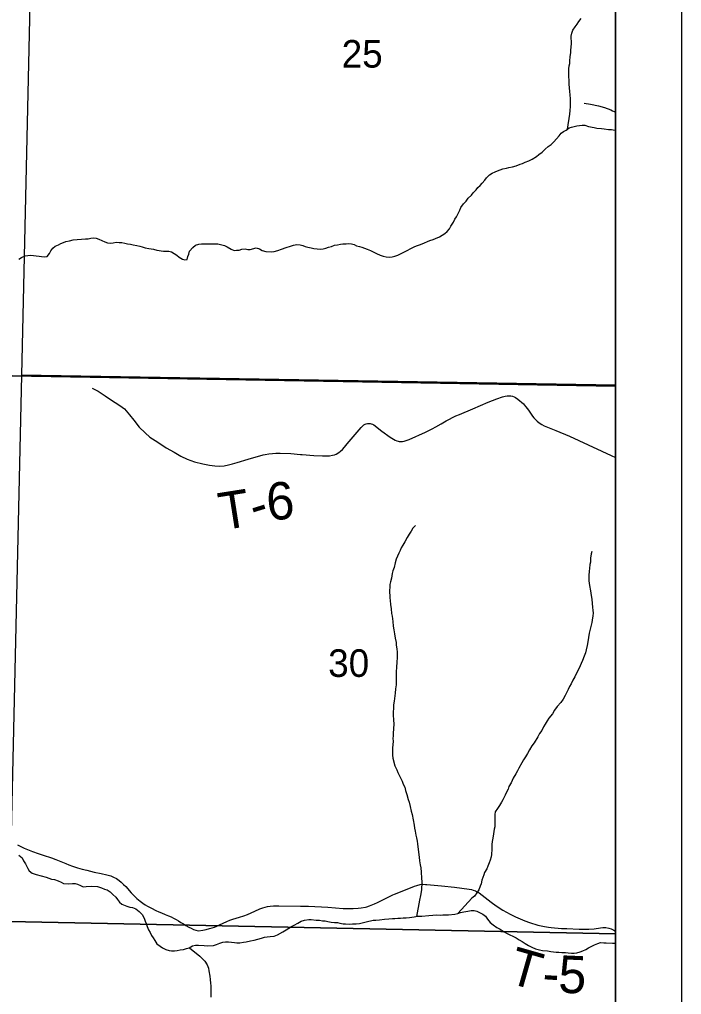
# Model space of a CAD drawing. Extents: x 0 to 34, y -8.9 to 22.
# Drawn here: x 29.612 to 30.617, y 11.088 to 12.568 of the extents above; entities that cross this region are included whole.
import ezdxf

# ---------------------------------------------------------------- set-up
doc = ezdxf.new("R2010")
doc.units = 0
for name, color, linetype in [('GM_X_Corporation', 7, 'Continuous'), ('GM_X_Minor_River', 7, 'Continuous'), ('GM_X_Section_Text', 7, 'Continuous'), ('GM_X_Township_Road', 7, 'Continuous'), ('GM_X_Township_Road_Text', 7, 'Continuous'), ('SH_Data', 7, 'Continuous')]:
    doc.layers.add(name, color=color, linetype=linetype)

msp = doc.modelspace()

# ---------------------------------------------------------------- linework, layer by layer
at = {"layer": 'GM_X_Corporation'}
for points in [[(28.7046, 7.104), (30.5167, 7.104), (30.5167, 13.904), (28.8143, 13.904), (28.8122, 13.7561), (28.8049, 13.053), (28.7787, 12.0377), (28.7786, 12.0342), (28.7779, 11.9899), (28.7762, 11.8872), (28.7797, 11.7437), (28.7775, 11.7346), (28.7754, 11.6346), (28.7651, 11.3014), (28.7622, 11.1187), (28.7609, 11.0119), (28.7377, 10.2012), (28.7308, 9.4444), (28.7238, 9.1729), (28.7123, 8.2818)], [(30.5167, 12.0118), (30.5167, 13.904), (28.8143, 13.904), (28.8122, 13.7561), (28.8049, 13.053), (28.7787, 12.0377), (28.8128, 12.0371), (28.9225, 12.0359), (29.2718, 12.0324), (29.364, 12.0313)], [(30.5167, 12.0133), (30.5167, 13.0305), (29.638, 13.0426), (29.6152, 12.0286)], [(28.7046, 7.104), (30.5167, 7.104), (30.5167, 12.0118), (29.364, 12.0313), (29.2718, 12.0324), (28.9225, 12.0359), (28.8128, 12.0371), (28.7787, 12.0377), (28.7786, 12.0342), (28.7779, 11.9899), (28.7762, 11.8872), (28.7797, 11.7437), (28.7775, 11.7346), (28.7754, 11.6346), (28.7651, 11.3014), (28.7622, 11.1187), (28.7609, 11.0119), (28.7377, 10.2012), (28.7308, 9.4444), (28.7238, 9.1729), (28.7123, 8.2818)], [(30.5167, 11.1804), (30.5167, 12.0133), (29.6152, 12.0286), (29.5966, 11.1991)], [(30.5167, 10.1744), (30.5167, 11.1804), (29.5966, 11.1991), (29.575, 10.1808)]]:
    msp.add_lwpolyline(points, close=True, dxfattribs=at)
at = {"layer": 'GM_X_Minor_River'}
msp.add_line((30.5153, 12.4003), (30.5167, 12.3999), dxfattribs=at)
for points in [[(30.4435, 12.402), (30.4472, 12.4245), (30.4475, 12.4302), (30.4481, 12.4366), (30.4484, 12.4427), (30.4483, 12.4484), (30.4478, 12.4537), (30.4473, 12.4598), (30.4469, 12.4643), (30.4464, 12.4707), (30.4463, 12.4764), (30.4458, 12.4813), (30.4456, 12.4935), (30.4463, 12.498), (30.447, 12.5018), (30.4473, 12.5056), (30.4479, 12.5117), (30.4486, 12.5182), (30.4489, 12.522), (30.4492, 12.5265), (30.4495, 12.5322), (30.4493, 12.5432), (30.4503, 12.5478), (30.4518, 12.552), (30.4551, 12.5573), (30.4584, 12.5616), (30.461, 12.5654), (30.4643, 12.57)], [(30.064, 12.2202), (30.0682, 12.2199), (30.0727, 12.2203), (30.0768, 12.2215), (30.081, 12.2227), (30.0855, 12.224), (30.09, 12.2256), (30.0949, 12.2264), (30.0991, 12.2272), (30.1028, 12.2277), (30.1078, 12.2281), (30.1115, 12.2282), (30.1157, 12.2279), (30.1199, 12.2268), (30.1237, 12.225), (30.1279, 12.2236), (30.1317, 12.2229), (30.1355, 12.2214), (30.1397, 12.22), (30.1446, 12.2178), (30.1538, 12.2134), (30.1595, 12.2109), (30.1641, 12.209), (30.1687, 12.208), (30.1732, 12.2077), (30.1777, 12.2081), (30.1815, 12.209), (30.1864, 12.2106), (30.1901, 12.2129), (30.2014, 12.2184), (30.2051, 12.2204), (30.2108, 12.2231), (30.2145, 12.2247), (30.219, 12.2263), (30.2232, 12.2279), (30.2348, 12.2327), (30.2397, 12.2343), (30.2435, 12.2362), (30.2495, 12.2386), (30.2536, 12.241), (30.2573, 12.2433), (30.2611, 12.2468), (30.2644, 12.2506), (30.2666, 12.2548), (30.2707, 12.261), (30.2725, 12.2652), (30.2751, 12.269), (30.2773, 12.2728), (30.2802, 12.279), (30.2816, 12.2828), (30.2861, 12.2885), (30.2898, 12.2928), (30.2927, 12.2974), (30.298, 12.3016), (30.3005, 12.3055), (30.305, 12.3097), (30.3076, 12.3136), (30.3113, 12.3163), (30.3143, 12.3201), (30.3184, 12.3244), (30.321, 12.3282), (30.3254, 12.3328), (30.3292, 12.3352), (30.3337, 12.3372), (30.3374, 12.3387), (30.3457, 12.3419), (30.351, 12.3428), (30.3547, 12.3436), (30.36, 12.3448), (30.3657, 12.3465), (30.3717, 12.3488), (30.3754, 12.35), (30.3796, 12.3516), (30.3852, 12.354), (30.3901, 12.3564), (30.3965, 12.3606), (30.4002, 12.3634), (30.405, 12.3672), (30.4099, 12.3715), (30.4144, 12.3754), (30.4188, 12.3789), (30.4229, 12.3827), (30.4311, 12.392), (30.4341, 12.3958), (30.4378, 12.3985), (30.4415, 12.4005), (30.446, 12.404), (30.4498, 12.4052), (30.4539, 12.406), (30.4577, 12.4069), (30.4619, 12.4077), (30.466, 12.4081), (30.4702, 12.4078), (30.4755, 12.406), (30.4839, 12.4047), (30.488, 12.4036), (30.4952, 12.403), (30.4994, 12.4023), (30.5059, 12.4016), (30.5104, 12.4013), (30.5153, 12.4003)], [(29.6109, 12.2046), (29.6151, 12.207), (29.6207, 12.2097), (29.629, 12.2106), (29.6335, 12.21), (29.6373, 12.2096), (29.6419, 12.209), (29.6457, 12.2086), (29.6502, 12.2083), (29.654, 12.2084), (29.6577, 12.213), (29.6595, 12.2172), (29.6625, 12.2211), (29.6662, 12.2242), (29.6711, 12.2265), (29.6748, 12.2285), (29.6786, 12.2301), (29.6824, 12.2313), (29.688, 12.2325), (29.6933, 12.2338), (29.7122, 12.2356), (29.7163, 12.2357), (29.7205, 12.2365), (29.7243, 12.237), (29.7284, 12.2366), (29.7326, 12.2352), (29.7418, 12.2308), (29.7456, 12.2294), (29.7505, 12.2287), (29.7543, 12.2295), (29.7588, 12.2304), (29.7634, 12.2301), (29.7672, 12.2297), (29.7717, 12.2291), (29.7759, 12.228), (29.7804, 12.2273), (29.7846, 12.2263), (29.7903, 12.2252), (29.7945, 12.2242), (29.7983, 12.2235), (29.8029, 12.222), (29.8082, 12.221), (29.8154, 12.2196), (29.8203, 12.2185), (29.8306, 12.2168), (29.8344, 12.2165), (29.8389, 12.2166), (29.8427, 12.2155), (29.8469, 12.2133), (29.8507, 12.2107), (29.8546, 12.2078), (29.8592, 12.2048), (29.863, 12.2034), (29.8667, 12.2042), (29.8674, 12.2084), (29.8689, 12.2122), (29.8703, 12.2168), (29.8751, 12.2222), (29.8792, 12.2256), (29.8841, 12.2276), (29.8883, 12.2281), (29.8921, 12.2278), (29.9057, 12.228), (29.9095, 12.2277), (29.9133, 12.2278), (29.9171, 12.2271), (29.9231, 12.2253), (29.9273, 12.2235), (29.9335, 12.2198), (29.9377, 12.2179), (29.9414, 12.218), (29.9452, 12.2185), (29.9497, 12.2197), (29.9543, 12.2201), (29.9584, 12.2194), (29.9622, 12.2195), (29.9713, 12.2219), (29.9762, 12.2205), (29.9804, 12.2179), (29.9857, 12.2161), (29.9948, 12.2155), (29.9986, 12.2164), (30.0039, 12.2176), (30.0099, 12.2196), (30.017, 12.2224), (30.0234, 12.2244), (30.028, 12.2256), (30.0329, 12.2268), (30.0382, 12.2262), (30.042, 12.2251), (30.0458, 12.2236), (30.0496, 12.2229), (30.0545, 12.2219), (30.0587, 12.2208), (30.064, 12.2202)], [(30.2129, 11.8003), (30.2088, 11.7964), (30.2066, 11.7918), (30.2033, 11.7869), (30.2003, 11.7819), (30.1967, 11.7757), (30.1937, 11.7704), (30.1915, 11.7665), (30.1897, 11.7623), (30.1875, 11.7581), (30.1839, 11.749), (30.1821, 11.7436), (30.1807, 11.7364), (30.1785, 11.7314), (30.1775, 11.7272), (30.1764, 11.7204), (30.175, 11.7147), (30.1743, 11.7109), (30.174, 11.7063), (30.1734, 11.7021), (30.1743, 11.6904), (30.1744, 11.6862), (30.1749, 11.6805), (30.1761, 11.6737), (30.1766, 11.6669), (30.1775, 11.6627), (30.1784, 11.6544), (30.1792, 11.6476), (30.1801, 11.6419), (30.181, 11.6359), (30.1822, 11.6294), (30.1838, 11.6226), (30.1839, 11.6188), (30.1848, 11.6132), (30.1852, 11.6082), (30.1853, 11.6014), (30.1848, 11.5915), (30.1841, 11.5866), (30.1835, 11.5764), (30.1836, 11.5714), (30.1837, 11.5669), (30.1838, 11.5585), (30.1828, 11.5521), (30.1822, 11.5456), (30.1805, 11.5334), (30.1798, 11.5281), (30.1795, 11.5228), (30.1793, 11.5167), (30.1793, 11.5125), (30.1798, 11.5053), (30.1803, 11.4989), (30.1791, 11.4848), (30.1791, 11.4811), (30.1788, 11.4769), (30.1789, 11.4727), (30.1786, 11.4674), (30.1783, 11.4628), (30.1781, 11.4556), (30.1781, 11.4518), (30.1786, 11.4469), (30.1818, 11.4356), (30.1846, 11.4292), (30.1862, 11.4254), (30.1909, 11.4164), (30.1928, 11.4119), (30.1944, 11.4077), (30.1968, 11.4028), (30.198, 11.3979), (30.2, 11.3919), (30.202, 11.3843), (30.2032, 11.3802), (30.2049, 11.3738), (30.2065, 11.3666), (30.2081, 11.3613), (30.2094, 11.3533), (30.211, 11.3454), (30.2115, 11.3409), (30.2127, 11.3363), (30.2136, 11.3299), (30.2144, 11.3261), (30.2153, 11.3212), (30.2161, 11.317), (30.2178, 11.3042), (30.2187, 11.2966), (30.2192, 11.2913), (30.2201, 11.2852), (30.2213, 11.2803), (30.2218, 11.2739), (30.2219, 11.2648), (30.2224, 11.2595), (30.2225, 11.2553), (30.2222, 11.2508), (30.2219, 11.247), (30.2205, 11.2386), (30.2191, 11.2313), (30.2147, 11.2068)], [(30.4807, 11.761), (30.4797, 11.7572), (30.4786, 11.7507), (30.4784, 11.7447), (30.4777, 11.7409), (30.477, 11.7348), (30.4767, 11.731), (30.4761, 11.7242), (30.4762, 11.7162), (30.4771, 11.709), (30.4784, 11.7011), (30.4792, 11.6973), (30.4805, 11.6878), (30.4813, 11.6825), (30.4818, 11.6757), (30.4823, 11.6719), (30.4824, 11.667), (30.4821, 11.6632), (30.481, 11.6567), (30.4807, 11.6529), (30.4786, 11.6449), (30.4775, 11.6411), (30.4765, 11.6369), (30.4755, 11.6304), (30.4744, 11.6236), (30.4734, 11.6183), (30.472, 11.6114), (30.471, 11.6068), (30.4691, 11.6019), (30.4666, 11.5954), (30.4644, 11.5908), (30.4615, 11.5839), (30.4582, 11.5782), (30.4549, 11.5705), (30.4516, 11.5655), (30.4491, 11.5598), (30.4465, 11.556), (30.4447, 11.5514), (30.4399, 11.5422), (30.437, 11.5368), (30.4337, 11.5315), (30.4281, 11.5253), (30.4237, 11.5199), (30.4207, 11.5145), (30.4155, 11.508), (30.4126, 11.5038), (30.4097, 11.4984), (30.4071, 11.4946), (30.4045, 11.4892), (30.4012, 11.4846), (30.3986, 11.4796), (30.3931, 11.4704), (30.3898, 11.4658), (30.3861, 11.4597), (30.3832, 11.4543), (30.3799, 11.4489), (30.3769, 11.4443), (30.3744, 11.4397), (30.37, 11.4321), (30.3678, 11.4279), (30.3652, 11.4233), (30.3612, 11.4167), (30.3583, 11.4095), (30.3549, 11.4041), (30.3535, 11.3999), (30.3509, 11.3953), (30.3491, 11.3911), (30.3455, 11.3838), (30.3433, 11.38), (30.3403, 11.3754), (30.3377, 11.3704), (30.334, 11.3658), (30.3334, 11.3616), (30.3335, 11.3525), (30.3336, 11.348), (30.3333, 11.343), (30.3326, 11.3392), (30.3312, 11.332), (30.3302, 11.3255), (30.3295, 11.3206), (30.3289, 11.316), (30.329, 11.3088), (30.3284, 11.3008), (30.3277, 11.297), (30.3263, 11.2924), (30.3248, 11.2882), (30.3226, 11.2833), (30.3212, 11.2791), (30.3179, 11.2737), (30.3168, 11.2699), (30.3154, 11.2657), (30.3139, 11.2619), (30.3125, 11.2565), (30.3111, 11.2527), (30.3089, 11.2473), (30.306, 11.2424), (30.3023, 11.2374), (30.2985, 11.2343), (30.2774, 11.2111)], [(29.6109, 11.2999), (29.6159, 11.2958), (29.6183, 11.2913), (29.6214, 11.2865), (29.6245, 11.2797), (29.6269, 11.2759), (29.6315, 11.2722), (29.6376, 11.2704), (29.6524, 11.2665), (29.6566, 11.2647), (29.6608, 11.2632), (29.665, 11.2626), (29.671, 11.2608), (29.6752, 11.2586), (29.6791, 11.2567), (29.687, 11.2561), (29.6927, 11.257), (29.6965, 11.257), (29.7003, 11.2556), (29.7048, 11.2538), (29.7087, 11.2519), (29.7132, 11.252), (29.7219, 11.2529), (29.7306, 11.2523), (29.7363, 11.2501), (29.7413, 11.2483), (29.7451, 11.2473), (29.7497, 11.2439), (29.7535, 11.2402)], [(29.7535, 11.2402), (29.7581, 11.2361), (29.7608, 11.2324), (29.7636, 11.2282), (29.7674, 11.2253), (29.775, 11.2224), (29.7796, 11.2206), (29.7838, 11.2202), (29.7887, 11.2184), (29.7937, 11.214), (29.7983, 11.2095), (29.8011, 11.2042), (29.8027, 11.1997), (29.8042, 11.1959), (29.8058, 11.1914), (29.8078, 11.1865), (29.8102, 11.1824), (29.8125, 11.1779), (29.8149, 11.1741), (29.8176, 11.17), (29.8207, 11.1651), (29.8253, 11.1618), (29.8291, 11.1592), (29.8341, 11.1566), (29.839, 11.1552), (29.8428, 11.1545), (29.8474, 11.1546), (29.8511, 11.155), (29.8557, 11.1559), (29.8609, 11.1567), (29.8655, 11.1579), (29.8696, 11.1592), (29.8745, 11.1619), (29.879, 11.1631), (29.8835, 11.1632), (29.8922, 11.1626), (29.8976, 11.1623), (29.9063, 11.1625), (29.9111, 11.1641), (29.916, 11.166), (29.9205, 11.1676), (29.9247, 11.1681), (29.9292, 11.1682), (29.9338, 11.1679), (29.9383, 11.1672), (29.9421, 11.1665), (29.9463, 11.1666), (29.9519, 11.1678), (29.9561, 11.1683), (29.9625, 11.1695), (29.9682, 11.1708), (29.9738, 11.1724), (29.9791, 11.174), (29.984, 11.1752), (29.9877, 11.176), (29.9927, 11.1761), (29.9983, 11.177), (30.0036, 11.179), (30.0118, 11.1833), (30.0167, 11.1864), (30.0208, 11.1891), (30.0246, 11.1915), (30.0287, 11.1935), (30.0343, 11.1966), (30.0396, 11.1997), (30.0448, 11.2009), (30.0509, 11.2022), (30.0546, 11.2019), (30.0622, 11.2013), (30.0672, 11.201), (30.0717, 11.2003), (30.0759, 11.2), (30.0801, 11.1989), (30.085, 11.1979), (30.0903, 11.1976), (30.0945, 11.1973), (30.0983, 11.1966), (30.1032, 11.1955), (30.107, 11.1956), (30.1127, 11.1949), (30.1172, 11.1954), (30.1229, 11.1955), (30.1278, 11.196), (30.1323, 11.1972), (30.1383, 11.1988), (30.1489, 11.2013), (30.1527, 11.2013), (30.1583, 11.2018), (30.1659, 11.2027), (30.1727, 11.2032), (30.178, 11.2037), (30.1818, 11.2037), (30.1863, 11.2042), (30.1901, 11.2043), (30.1942, 11.2047), (30.1988, 11.2048), (30.2037, 11.2053), (30.2112, 11.2062), (30.2161, 11.207), (30.2226, 11.2071), (30.2335, 11.2081)], [(30.2335, 11.2081), (30.2452, 11.209), (30.2502, 11.2087), (30.2547, 11.2092), (30.263, 11.2094), (30.2725, 11.2103), (30.2774, 11.2111), (30.2811, 11.2127), (30.2864, 11.2139), (30.2924, 11.2148), (30.2973, 11.2157), (30.3019, 11.2157), (30.3061, 11.2147), (30.3103, 11.2128), (30.3152, 11.2103), (30.3191, 11.2073), (30.3225, 11.2028), (30.3264, 11.1976), (30.331, 11.1942), (30.3364, 11.1898), (30.3414, 11.1872), (30.3475, 11.1835), (30.3513, 11.1813), (30.3658, 11.1744), (30.3704, 11.1714), (30.375, 11.1688), (30.3796, 11.1655), (30.3846, 11.1626), (30.3895, 11.16), (30.3949, 11.1574), (30.4013, 11.156), (30.4055, 11.155), (30.4131, 11.1543), (30.4184, 11.1537), (30.4226, 11.153), (30.4264, 11.1527), (30.4305, 11.1524), (30.4351, 11.1521), (30.4404, 11.1518), (30.4445, 11.1515), (30.4495, 11.1508), (30.454, 11.1509), (30.4578, 11.1513), (30.4631, 11.1529), (30.4672, 11.1545), (30.4717, 11.1565), (30.4754, 11.1589), (30.4796, 11.1612), (30.4848, 11.1636), (30.4897, 11.1659), (30.4938, 11.1672), (30.4988, 11.1669), (30.5025, 11.1665), (30.512, 11.166), (30.5162, 11.1664), (30.5167, 11.1665)], [(29.8699, 11.1593), (29.8857, 11.1462), (29.8896, 11.1424), (29.8934, 11.1391), (29.8969, 11.1331), (29.8989, 11.1282), (29.8994, 11.1244), (29.901, 11.1161), (29.9015, 11.1111), (29.902, 11.1055), (29.9024, 11.1013), (29.9025, 11.096), (29.9022, 11.0899), (29.9023, 11.0842)]]:
    msp.add_lwpolyline(points, dxfattribs=at)
at = {"layer": 'GM_X_Township_Road'}
for points in [[(30.4688, 12.4415), (30.4784, 12.4398), (30.4906, 12.4374), (30.4997, 12.4346), (30.5092, 12.4311), (30.5118, 12.4299), (30.5144, 12.4287), (30.5167, 12.4276)], [(29.7224, 12.0087), (29.7317, 12.0041), (29.7422, 11.9971), (29.7501, 11.9916), (29.7572, 11.987), (29.7645, 11.9825), (29.7712, 11.9772), (29.7789, 11.9685), (29.7856, 11.96), (29.7939, 11.9495), (29.8026, 11.9409), (29.8101, 11.9346), (29.8218, 11.9268), (29.8347, 11.9182), (29.8467, 11.9114), (29.8571, 11.9054), (29.8666, 11.9009), (29.8777, 11.8968), (29.8902, 11.8937), (29.9002, 11.8918), (29.9085, 11.8906), (29.9149, 11.8903), (29.9227, 11.891), (29.9291, 11.8924), (29.9352, 11.8939), (29.9424, 11.8959), (29.9593, 11.9008), (29.9818, 11.9073), (29.9849, 11.908), (29.9903, 11.9089), (29.9958, 11.9096), (30.0013, 11.9101), (30.0078, 11.9102), (30.0237, 11.9095), (30.0385, 11.9082), (30.041, 11.9079), (30.0587, 11.9065), (30.0717, 11.906), (30.0825, 11.9062), (30.0873, 11.9068), (30.09, 11.9076), (30.0926, 11.9087), (30.0965, 11.9111), (30.099, 11.9131), (30.1021, 11.9158), (30.1054, 11.9193), (30.1095, 11.9244), (30.1305, 11.9492), (30.1348, 11.953), (30.1365, 11.954), (30.1383, 11.9547), (30.1402, 11.9552), (30.1421, 11.9553), (30.1441, 11.9552), (30.1459, 11.9547), (30.1479, 11.9539), (30.1497, 11.9529), (30.162, 11.9436), (30.1746, 11.9344), (30.1794, 11.9312), (30.1824, 11.9296), (30.1847, 11.9288), (30.1867, 11.9283), (30.1883, 11.928), (30.1907, 11.9279), (30.1932, 11.928), (30.1956, 11.9285), (30.2036, 11.9308), (30.2282, 11.9421), (30.2383, 11.947), (30.244, 11.9498), (30.2522, 11.9544), (30.2595, 11.959), (30.2644, 11.9617), (30.2694, 11.9643), (30.2744, 11.9668), (30.2796, 11.9689), (30.2998, 11.9774), (30.3233, 11.9875), (30.3366, 11.9927), (30.345, 11.9955), (30.3492, 11.9966), (30.3521, 11.9971), (30.3576, 11.997), (30.3603, 11.9964), (30.3629, 11.9956), (30.3649, 11.9947), (30.3684, 11.9921), (30.377, 11.9848), (30.3801, 11.9811), (30.383, 11.9773), (30.3854, 11.974), (30.3884, 11.9695), (30.3905, 11.9664), (30.3928, 11.9636), (30.3949, 11.9611), (30.3974, 11.9588), (30.4008, 11.9562), (30.4046, 11.9538), (30.4084, 11.9518), (30.4133, 11.9495), (30.4258, 11.9445), (30.4467, 11.9357), (30.4607, 11.9293), (30.5098, 11.9065), (30.5167, 11.9034)], [(29.6091, 11.3153), (29.6192, 11.3106), (29.6316, 11.3055), (29.6402, 11.3022), (29.6481, 11.2997), (29.6606, 11.2955), (29.6672, 11.2931), (29.675, 11.2901), (29.6823, 11.2871), (29.687, 11.2851), (29.6923, 11.2832), (29.7002, 11.2806), (29.707, 11.2785), (29.7142, 11.2768), (29.7255, 11.2741), (29.736, 11.2719), (29.7446, 11.2698), (29.7506, 11.2682), (29.7545, 11.2666), (29.7593, 11.2642), (29.7633, 11.2615), (29.7666, 11.2586), (29.7697, 11.2553), (29.7732, 11.252), (29.7815, 11.2427), (29.786, 11.2378), (29.7901, 11.234), (29.795, 11.2301), (29.799, 11.2271), (29.803, 11.2243), (29.8063, 11.2223), (29.8126, 11.2191), (29.819, 11.2158), (29.8237, 11.2137), (29.8278, 11.212), (29.8329, 11.2098), (29.8382, 11.2077), (29.8424, 11.206), (29.846, 11.2042), (29.8496, 11.2021), (29.8532, 11.2001), (29.857, 11.1977), (29.8607, 11.1953), (29.8647, 11.193), (29.8688, 11.1905), (29.8725, 11.1888), (29.876, 11.187), (29.8799, 11.1857), (29.8838, 11.1851), (29.8902, 11.1857), (29.8953, 11.1868), (29.9005, 11.1882), (29.9043, 11.1893), (29.9079, 11.1907), (29.9113, 11.1921), (29.9155, 11.1938), (29.9265, 11.1989), (29.9312, 11.201), (29.936, 11.2027), (29.946, 11.2057), (29.9523, 11.2075), (29.958, 11.2097), (29.9694, 11.215), (29.977, 11.2183), (29.9814, 11.2198), (29.9848, 11.2208), (29.9886, 11.2217), (29.9925, 11.2223), (29.9977, 11.2228), (30.0056, 11.223), (30.0385, 11.2225), (30.0505, 11.2223), (30.0802, 11.2208), (30.1035, 11.219), (30.1125, 11.2187), (30.1185, 11.2188), (30.1258, 11.2193), (30.1306, 11.2199), (30.137, 11.221), (30.1392, 11.2215), (30.1432, 11.2227), (30.1508, 11.2257), (30.1551, 11.2277), (30.1787, 11.2395), (30.181, 11.2405), (30.1928, 11.2453), (30.2117, 11.2525), (30.2152, 11.2539), (30.2202, 11.2551), (30.2239, 11.2555), (30.228, 11.2553)], [(30.228, 11.2553), (30.2301, 11.2552), (30.2527, 11.253), (30.272, 11.2512), (30.2946, 11.2483), (30.2979, 11.2477), (30.3007, 11.2468), (30.3039, 11.2456), (30.3058, 11.2447), (30.3074, 11.2437), (30.3094, 11.2425), (30.3279, 11.2282), (30.3355, 11.2228), (30.3458, 11.2164), (30.3568, 11.2103), (30.365, 11.2063), (30.3719, 11.2032), (30.379, 11.2002), (30.3862, 11.1975), (30.3987, 11.1936), (30.4037, 11.1923), (30.4087, 11.1913), (30.4148, 11.1904), (30.4187, 11.1899), (30.4346, 11.1886), (30.4425, 11.1882), (30.4613, 11.1875), (30.4763, 11.1872), (30.4842, 11.188), (30.4939, 11.1897), (30.4973, 11.1901), (30.5019, 11.1898), (30.5065, 11.189), (30.5099, 11.1877), (30.5142, 11.1858), (30.5167, 11.1845)]]:
    msp.add_lwpolyline(points, dxfattribs=at)
at = {"layer": 'SH_Data'}
for points in [[(23.6167, 14.004), (30.6167, 14.004), (30.6167, 7.004), (23.6167, 7.004)], [(23.7167, 13.904), (30.5167, 13.904), (30.5167, 7.104), (23.7167, 7.104)]]:
    msp.add_lwpolyline(points, close=True, dxfattribs=at)

# ---------------------------------------------------------------- texts
at = {"layer": 'GM_X_Section_Text'}
for s, p in [('25', (30.101, 12.4954)), ('30', (30.0805, 11.5704))]:
    msp.add_text(s, height=0.04186, rotation=0, dxfattribs=at).set_placement(p)
at = {"layer": 'GM_X_Township_Road_Text'}
for s, rotation, p in [('6', 4.6573, (29.9889, 11.8077)), ('T', 8.9762, (29.9191, 11.7928)), ('-', 17.2386, (29.9698, 11.8014)), ('T', 344.0364, (30.3507, 11.1067)), ('5', 357.5471, (30.429, 11.0912)), ('-', 356.4484, (30.4046, 11.0928))]:
    msp.add_text(s, height=0.0568, rotation=rotation, dxfattribs=at).set_placement(p)

doc.saveas('drawing.dxf')
